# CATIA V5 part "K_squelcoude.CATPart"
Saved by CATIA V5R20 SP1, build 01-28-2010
Part number: squelcoude
Publications: "Longueurcotecoude", "longueurdroitepivot"
Bounding box of the stored display mesh (mm): x 0 to 80, y 0 to 80, z -15 to 15
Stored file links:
  G:\Khaled_CFAO_2011\SIL\SIL_GR2\zthiebault\Khaled\CAD_ThinkMOTION\K_squelcoude.CATPart
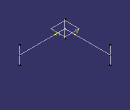
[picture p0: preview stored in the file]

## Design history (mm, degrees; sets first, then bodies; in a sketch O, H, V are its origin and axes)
Parameters
  Longueurcotecoude = 80 mm
  longueurdroitepivot = 30 mm
Set1 "setgéomcoude"
  Sketch1 on xy-plane, origin (0, 0, 0), H (1, 0, 0), V (0, 1, 0)
    point P1 (0, 80)
    line L1 (0, 80) -> (0, 0)
    line L2 (0, 0) -> (80, 0)
    point P2 (80, 0)
    length L2 = 80 {= Longueurcotecoude}
    length L1 = 80 {= Longueurcotecoude}
    coincidence: P1 V
    vertical: L1 V
    horizontal: L2 H
  Line1: type Normal, RefPoint Sketch1.P2, RefSkin xy-plane, Start -15 {= -longueurdroitepivot /2}, End 15 {= longueurdroitepivot /2}
  Line2: type Normal, RefPoint Sketch1.P1, RefSkin xy-plane, Start -15 {= -longueurdroitepivot /2}, End 15 {= longueurdroitepivot /2}
  Line3: type Normal, RefPoint vertex [element of Sketch1 | element of Sketch1], RefSkin xy-plane, Start -15 {= -longueurdroitepivot /2}, End 15 {= longueurdroitepivot /2}
  Plane1: type OffsetPt, RefPlane xy-plane, RefPoint Sketch1.P1
  Plane2: type OffsetPt, RefPlane xy-plane, RefPoint Sketch1.P2
Body1 (main body)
